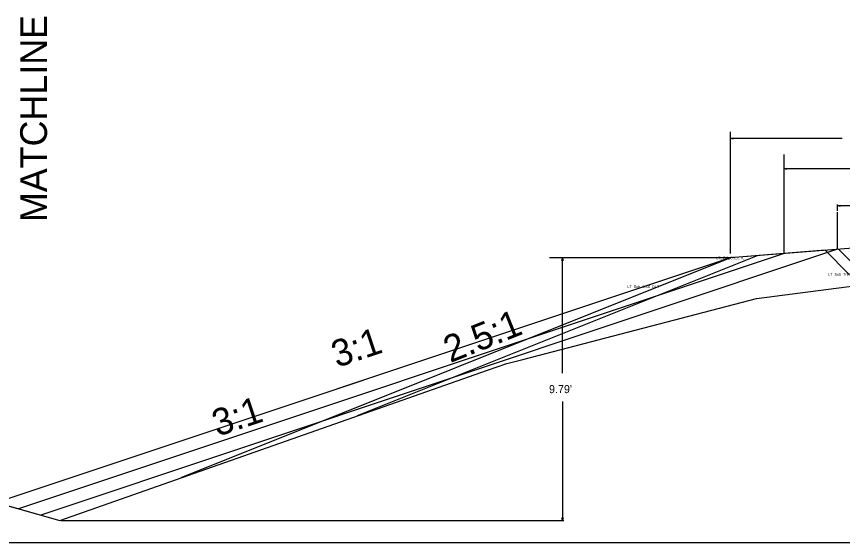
# Model space of a CAD drawing. Extents: x 2207892 to 2209721, y 61220 to 65449.
# Drawn here: x 2208063.25 to 2208094.07, y 64407.31 to 64426.93 of the extents above; entities that cross this region are included whole.
import ezdxf

# ---------------------------------------------------------------- set-up
doc = ezdxf.new("R2010")
doc.units = 0
for name, color, linetype in [('Exist DTM Breakline Cogo Comment', 7, 'Continuous'), ('Exist DTM Breakline Cogo Elevation', 7, 'Continuous'), ('Exist DTM Ridgeline Cogo Comment', 7, 'Continuous'), ('Exist Hydro Stream or Body of Water Cogo Elevation', 7, 'Continuous'), ('Exist Other Culture Fence Line Cogo Elevation', 7, 'Continuous'), ('Exist Roads EOP Other', 7, 'Continuous'), ('Exist Roads EOP Other Cogo Elevation', 7, 'Continuous'), ('Exist Roads EOP Other Cogo Number', 7, 'Continuous'), ('Exist Structure Minor Head and End Wall Cogo Point CELL', 7, 'Continuous')]:
    doc.layers.add(name, color=color, linetype=linetype)

msp = doc.modelspace()

# ---------------------------------------------------------------- linework, layer by layer
at = {"layer": 'Exist DTM Breakline Cogo Comment'}
msp.add_lwpolyline([(2208064.863, 64408.136), (2208080.823, 64413.744), (2208081.546, 64413.99), (2208082.147, 64414.133), (2208090.865, 64416.412), (2208096.235, 64417.116), (2208098.977, 64417.457), (2208099.385, 64417.617), (2208094.327, 64417.314), (2208093.43, 64418.211), (2208089.891, 64417.928), (2208062.5, 64408.797)], close=True, dxfattribs=at)
at = {"layer": 'Exist Hydro Stream or Body of Water Cogo Elevation'}
msp.add_lwpolyline([(2208095.891, 64418.408), (2208089.891, 64417.928), (2208060.529, 64408.14)], dxfattribs=at)
at = {"layer": 'Exist Other Culture Fence Line Cogo Elevation'}
msp.add_line((2208094.827, 64417.344), (2208093.921, 64418.25), dxfattribs=at)
at = {"layer": 'Exist Roads EOP Other'}
for p, q in [((2208089.891, 64418.088), (2208089.891, 64422.638)), ((2208089.891, 64418.138), (2208089.891, 64422.431)), ((2208094.062, 64422.381), (2208089.891, 64422.381)), ((2208091.891, 64418.088), (2208091.891, 64421.791)), ((2208091.891, 64418.138), (2208091.891, 64421.302)), ((2208095.037, 64421.252), (2208091.891, 64421.252)), ((2208093.891, 64419.688), (2208093.891, 64419.921)), ((2208096.089, 64419.871), (2208093.891, 64419.871)), ((2208093.891, 64418.248), (2208093.891, 64419.638)), ((2208093.891, 64418.248), (2208064.153, 64408.335)), ((2208091.891, 64418.088), (2208063.326, 64408.566)), ((2208090.891, 64418.008), (2208075.957, 64412.034)), ((2208089.891, 64417.928), (2208069.38, 64409.723)), ((2208089.891, 64417.928), (2208083.142, 64417.928)), ((2208085.433, 64417.928), (2208083.571, 64417.928)), ((2208083.621, 64413.628), (2208083.621, 64417.928)), ((2208083.621, 64412.575), (2208083.621, 64408.136)), ((2208064.913, 64408.136), (2208083.671, 64408.136))]:
    msp.add_line(p, q, dxfattribs=at)
for points in [[(2208089.991, 64422.356), (2208089.891, 64422.381), (2208089.991, 64422.406)], [(2208091.991, 64421.227), (2208091.891, 64421.252), (2208091.991, 64421.277)], [(2208093.991, 64419.846), (2208093.891, 64419.871), (2208093.991, 64419.896)], [(2208083.596, 64417.828), (2208083.621, 64417.928), (2208083.646, 64417.828)], [(2208083.646, 64408.236), (2208083.621, 64408.136), (2208083.596, 64408.236)]]:
    msp.add_lwpolyline(points, dxfattribs=at)
at = {"layer": 'Exist Roads EOP Other Cogo Elevation'}
msp.add_lwpolyline([(2208062.438, 64408.815), (2208064.863, 64408.136), (2208080.823, 64413.744), (2208081.546, 64413.99), (2208082.147, 64414.133), (2208090.865, 64416.412), (2208096.235, 64417.116)], dxfattribs=at)
at = {"layer": 'Exist Roads EOP Other Cogo Number'}
msp.add_line((2207918.174, 64407.31), (2208118.174, 64407.31), dxfattribs=at)

# ---------------------------------------------------------------- texts
at = {"layer": 'Exist DTM Breakline Cogo Elevation'}
msp.add_text('MATCHLINE', height=1, rotation=90, dxfattribs=at).set_placement((2208064.388, 64419.265))
at = {"layer": 'Exist DTM Ridgeline Cogo Comment'}
msp.add_text('3:1', height=1, rotation=18.4332, dxfattribs=at).set_placement((2208075.206, 64413.824))
at = {"layer": 'Exist Roads EOP Other'}
for s, rotation, p in [('2.5:1', 21.8014, (2208079.436, 64414.002)), ('3:1', 18.4349, (2208070.754, 64411.254))]:
    msp.add_text(s, height=1, rotation=rotation, dxfattribs=at).set_placement(p)
msp.add_text("9.79'", height=0.3, dxfattribs=at).set_placement((2208083.12, 64412.882))
at = {"layer": 'Exist Structure Minor Head and End Wall Cogo Point CELL'}
for s, p in [('LT_GS_OS_CTL', (2208089.36, 64417.878)), ('LT_Sub_Trench_Out', (2208093.537, 64417.264)), ('LT_Sub_OSS_DLT', (2208086.041, 64416.805))]:
    msp.add_text(s, height=0.1, dxfattribs=at).set_placement(p)

doc.saveas('drawing.dxf')
